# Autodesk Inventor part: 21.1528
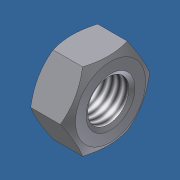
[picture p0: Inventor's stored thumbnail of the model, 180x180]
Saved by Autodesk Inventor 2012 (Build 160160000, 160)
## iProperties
Created: 2006-02
Part Number: 21.1528
Material: Steel, Mild
Description: M12 HEX NUT
Document SubType Name: Modeling
Standard: DIN 934
Designer: Andy Moles
Standards Organization: DIN
Language: en-US
Size Designation: M12
Categories: <MemberInstance><Categories><Category DisplayName="Fasteners" InternalName="e4da775c-781d-43d5-af7c-5136215cf5a6" Mnemonic="FSTN"><Category DisplayName="Nuts" I
Density: 7.86 g/cm^3
Mass: 17.5637 g
Surface Area: 13.3413 cm^2
Volume: 2.23456 cm^3
Author: Andy Moles
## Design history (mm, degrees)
body "Solid1"
workaxis "Work Axis1"
workplane "Work Plane1"
sketch "Sketch1"
  geometry: L1 (-10.97, 0)-(-5.485, 9.5); L2 (-5.485, 9.5)-(5.485, 9.5); L3 (5.485, 9.5)-(10.97, 0); L4 (10.97, 0)-(5.485, -9.5); L5 (5.485, -9.5)-(-5.485, -9.5); L6 (-5.485, -9.5)-(-10.97, 0); 2 further points
  constraints: 12 end point, 1 coincident, 1 horizontal, 11 other
  dimensions: "d0" = 21.93931 distance of L3.end L1.start (= 1.1547 x SW)
extrude "Body" new body sketch "Sketch1" distance "d1" = 10 (= KOH); taper "d2" = 0 deg
revolve "Chamfer1" stored, may be unused: angle "d7" = 90 deg
sketch "Sketch3"
  geometry: 4 further points
  constraints: 1 coincident, 1 other
hole "Thread" sketch "Sketch3" diameter "d25" = 10.106; stored, may be unused: countersink angle "d29" = 82 deg, drill point angle "d31" = 118 deg; dims "d26" = 6, "d27" = 4, "d28" = 2, "d30" = 8
chamfer "Chamfer2" distance "d8" = 0.94722 (= -0.5 x GD1 + 0.5 x NND); stored, may be unused: angle "d9" = 30 deg, second distance "d40" = 0.94722 (= -0.5 x GD1 + 0.5 x NND)
chamfer "Chamfer3" distance "d10" = 0.94722 (= -0.5 x GD1 + 0.5 x NND); stored, may be unused: angle "d11" = 30 deg, second distance "d41" = 0.94722 (= -0.5 x GD1 + 0.5 x NND)
sketch "Sketch2"
  geometry: L1 (0, 5.485)-(0, 10.97) reference; L2 (0, 10.97)-(10, 10.97) reference; L3 (10, 5.485)-(10, 10.97) reference; L4 (-1, 0)-(13, 0) reference; L5 (1.368, 10.97)-(0, 8.6); L6 (8.632, 10.97)-(10, 8.6)
  constraints: 4 end point, 4 point on line
  dimensions: "d3" = 30 deg angle of L1 L5 (= ANG1); "d4" = 30 deg angle of L3 L6 (= ANG2); "d5" = 17.2 diameter of L5.end L4 (= SW0); "d6" = 17.2 diameter of L6.end L4 (= SW01)
other parameters: "ANG1" = 30 deg [user parameter; used in 1 equation term], "ANG2" = 30 deg [user parameter; used in 1 equation term], "NND" = 12 [user parameter; used in 4 equation terms], "KOH" = 10 [user parameter; used in 1 equation term], "SW" = 19 [user parameter; used in 2 equation terms], "SW0" = 17.2 (= SW01) [user parameter; used in 1 equation term], "SW01" = 17.2 [user parameter; used in 2 equation terms], "GD1" = 10.10557 (computed from THREADDIA, PTC, TOA) [user parameter; used in 4 equation terms], "d13" = 0, "d14" = 0, "d39" = 0, "d42" = 0, "GUL" = 0.94722 (= 0.541266 x PTC) [user parameter], "TPU" = 5.71429 (computed from PTC) [user parameter], "THREADDIA" = 12 [user parameter; used in 1 equation term], "TOA" = 30 deg [user parameter; used in 1 equation term], "PTC" = 1.75 [user parameter; used in 4 equation terms], "E0" = 21.945 (= 1.155 x SW) [user parameter], "GAL" = 0.94722 (= 0.541266 x PTC) [user parameter]
